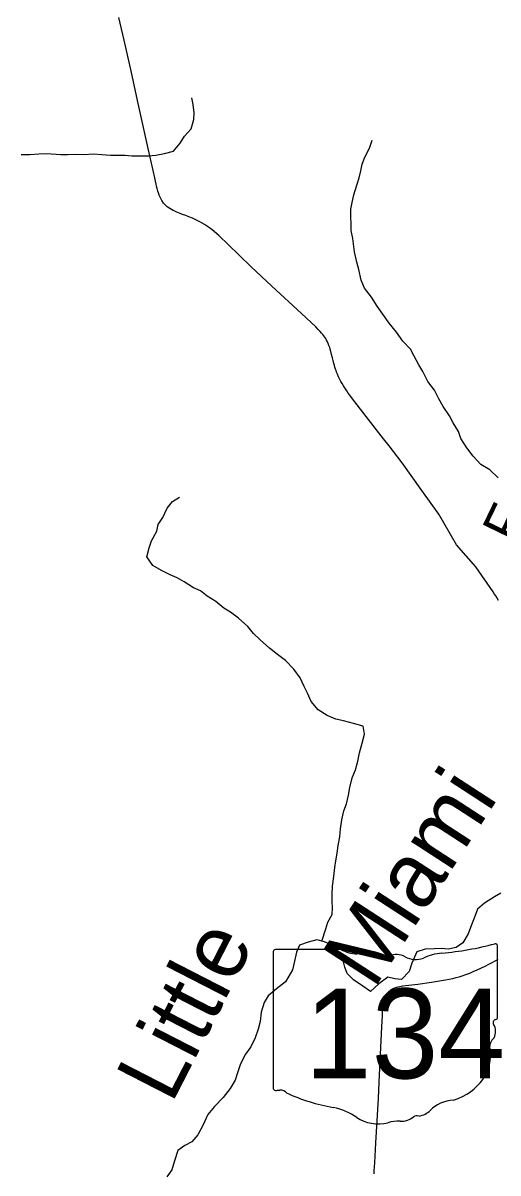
# Model space of a CAD drawing. Extents: x 0 to 1052, y -194 to 246.
# Drawn here: x 3.805 to 4.503, y 17.846 to 19.536 of the extents above; entities that cross this region are included whole.
import ezdxf

# ---------------------------------------------------------------- set-up
doc = ezdxf.new("R2010")
doc.units = 0
for name, color, linetype in [('GM_X_County_Road_Text', 7, 'Continuous'), ('GM_X_Major_River', 7, 'Continuous'), ('GM_X_Major_River_Text', 7, 'Continuous'), ('GM_X_Minor_River', 7, 'Continuous'), ('GM_X_State_Location', 7, 'Continuous'), ('GM_X_State_Route', 7, 'Continuous'), ('GM_X_State_Shield', 7, 'Continuous')]:
    doc.layers.add(name, color=color, linetype=linetype)

msp = doc.modelspace()

# ---------------------------------------------------------------- linework, layer by layer
at = {"layer": 'GM_X_Major_River'}
msp.add_lwpolyline([(4.5075, 18.2574), (4.4979, 18.2519), (4.4833, 18.2424), (4.4732, 18.2338), (4.468, 18.2207), (4.4644, 18.2105), (4.4595, 18.1973), (4.4517, 18.1842), (4.442, 18.1775), (4.4298, 18.1751), (4.42, 18.1761), (4.4094, 18.1755), (4.3961, 18.1751), (4.3838, 18.1708), (4.3767, 18.1546), (4.3726, 18.1421), (4.3613, 18.1302), (4.3515, 18.1312), (4.3413, 18.1337), (4.3282, 18.1241), (4.3158, 18.1125), (4.3046, 18.1204), (4.2911, 18.1301), (4.2814, 18.139), (4.2782, 18.1486), (4.2758, 18.1581), (4.2707, 18.1685), (4.2618, 18.1797), (4.2483, 18.1856), (4.2369, 18.1885), (4.2243, 18.185), (4.2113, 18.1807), (4.207, 18.1705), (4.204, 18.1573), (4.2011, 18.1445), (4.1909, 18.1268), (4.1777, 18.1165), (4.1654, 18.1065), (4.1595, 18.0967), (4.1554, 18.0824), (4.1536, 18.0688), (4.1507, 18.0574), (4.1466, 18.0446), (4.1399, 18.0315), (4.1321, 18.0206), (4.1249, 18.0063), (4.1205, 17.9932), (4.1168, 17.9826), (4.1094, 17.9702), (4.0992, 17.9572), (4.0864, 17.9437), (4.077, 17.9318), (4.0695, 17.916), (4.062, 17.9021), (4.0534, 17.892), (4.0431, 17.8866), (4.0327, 17.8792), (4.0278, 17.8637), (4.0241, 17.8505), (4.0167, 17.8404)], dxfattribs=at)
at = {"layer": 'GM_X_Minor_River'}
for points in [[(3.8025, 19.3424), (3.8154, 19.3426), (3.8283, 19.3436), (3.8397, 19.3442), (3.861, 19.3424), (3.8708, 19.3427), (3.8834, 19.3429), (3.8944, 19.3427), (3.9088, 19.3433), (3.921, 19.3428), (3.9339, 19.3418), (3.9551, 19.3416), (3.965, 19.3407), (3.9783, 19.3405), (3.9897, 19.3407), (4.0003, 19.3414), (4.0133, 19.3442), (4.0263, 19.3475), (4.0363, 19.3591), (4.0425, 19.3693), (4.0525, 19.3805), (4.0561, 19.3938), (4.0566, 19.4036), (4.0553, 19.4158), (4.0531, 19.4257)], [(4.5034, 18.8675), (4.4914, 18.8794), (4.4778, 18.8872), (4.467, 18.8991), (4.4573, 18.9114), (4.4487, 18.9255), (4.4451, 18.9355), (4.4376, 18.9485), (4.4321, 18.9588), (4.4227, 18.9722), (4.4164, 18.9837), (4.4098, 18.9963), (4.4001, 19.0089), (4.3927, 19.0238), (4.3871, 19.0334), (4.3801, 19.046), (4.3745, 19.0567), (4.3636, 19.0683), (4.3539, 19.0817), (4.3431, 19.0947), (4.3364, 19.1043), (4.3256, 19.1196), (4.3174, 19.133), (4.3073, 19.146), (4.3022, 19.1579), (4.2986, 19.1735), (4.2957, 19.1845), (4.2925, 19.1994), (4.2897, 19.2192), (4.2876, 19.231), (4.2873, 19.2405), (4.2871, 19.2507), (4.2872, 19.2621), (4.2889, 19.2719), (4.2913, 19.2833), (4.2957, 19.2977), (4.2992, 19.3083), (4.3016, 19.3185), (4.3037, 19.3283), (4.3076, 19.3385), (4.3142, 19.3517), (4.3182, 19.3634)], [(4.2445, 18.1866), (4.2503, 18.2046), (4.2531, 18.2144), (4.2593, 18.2261), (4.2598, 18.2356), (4.2596, 18.2454), (4.2597, 18.2553), (4.2602, 18.2674), (4.2619, 18.2815), (4.2633, 18.2947), (4.2649, 18.3046), (4.267, 18.3159), (4.2686, 18.3273), (4.2707, 18.3398), (4.2716, 18.3516), (4.2737, 18.3648), (4.2765, 18.3781), (4.2805, 18.3883), (4.2837, 18.4011), (4.2857, 18.4125), (4.289, 18.4265), (4.2937, 18.4382), (4.2973, 18.4511), (4.2997, 18.4636), (4.3037, 18.4776), (4.3073, 18.4908), (4.3052, 18.5026), (4.2908, 18.5066), (4.276, 18.5106), (4.2651, 18.513), (4.2522, 18.5181), (4.239, 18.5266), (4.2289, 18.5389), (4.2234, 18.5511), (4.2186, 18.5607), (4.2127, 18.5737), (4.2034, 18.5863), (4.191, 18.599), (4.179, 18.6079), (4.1673, 18.6171), (4.1538, 18.6295), (4.1441, 18.6387), (4.1358, 18.6491), (4.1219, 18.6614), (4.1103, 18.6699), (4.1005, 18.6761), (4.0885, 18.6857), (4.0757, 18.6935), (4.0659, 18.7012), (4.0557, 18.7059), (4.0418, 18.7148), (4.0316, 18.7206), (4.0214, 18.725), (4.0085, 18.7312), (3.9961, 18.7386), (3.9872, 18.7516), (3.9908, 18.7648), (3.9939, 18.775), (4.0017, 18.789), (4.0038, 18.7988), (4.0107, 18.8094), (4.017, 18.823), (4.0251, 18.8327), (4.0351, 18.839)]]:
    msp.add_lwpolyline(points, dxfattribs=at)
at = {"layer": 'GM_X_State_Route'}
for points in [[(4.504, 18.6871), (4.502, 18.6907), (4.4999, 18.6939), (4.4982, 18.6966), (4.496, 18.7), (4.4706, 18.7369), (4.4423, 18.7689), (4.4161, 18.8139), (4.3914, 18.849), (4.3624, 18.8893), (4.3432, 18.9144), (4.335, 18.9246), (4.3095, 18.9576), (4.2879, 18.9857), (4.2856, 18.9888), (4.2832, 18.9921), (4.281, 18.9952), (4.2781, 18.9996), (4.2761, 19.0025), (4.2741, 19.006), (4.2723, 19.009), (4.2705, 19.0127), (4.269, 19.0157), (4.2673, 19.0196), (4.266, 19.0226), (4.2652, 19.0251), (4.2644, 19.0272), (4.2634, 19.0303), (4.2628, 19.0327), (4.2621, 19.0354), (4.2609, 19.04), (4.2599, 19.0439), (4.2588, 19.0485), (4.2577, 19.0533), (4.2568, 19.0564), (4.2559, 19.0592), (4.2548, 19.062), (4.2537, 19.0649), (4.2525, 19.0675), (4.2514, 19.0699), (4.2501, 19.0721), (4.2489, 19.0741), (4.2475, 19.0759), (4.246, 19.078), (4.2441, 19.0802), (4.2419, 19.0826), (4.2392, 19.0854), (4.2354, 19.0892), (4.2146, 19.1087), (4.1707, 19.1491), (4.1403, 19.1777), (4.1225, 19.195), (4.1074, 19.2098), (4.093, 19.2234), (4.09, 19.2261), (4.0861, 19.2296), (4.0832, 19.2319), (4.0793, 19.2349), (4.0763, 19.2369), (4.0721, 19.2397), (4.0686, 19.2417), (4.0652, 19.2437), (4.0613, 19.2456), (4.0574, 19.2475), (4.0541, 19.2489), (4.0489, 19.2511), (4.0443, 19.2528), (4.0396, 19.2545), (4.0359, 19.2559), (4.0314, 19.2577), (4.0285, 19.2591), (4.0257, 19.2604), (4.0209, 19.2633), (4.0172, 19.2658), (4.0143, 19.2684), (4.0118, 19.2712), (4.0092, 19.2749), (4.0071, 19.2787), (4.0053, 19.2828), (4.0041, 19.286), (4.0033, 19.2888), (4.0024, 19.2925), (4.0015, 19.296), (4.0008, 19.2991), (3.9998, 19.3034), (3.9988, 19.3081), (3.9891, 19.3512), (3.9743, 19.4173), (3.9644, 19.4628), (3.9537, 19.5107), (3.9461, 19.544)], [(4.3212, 17.8447), (4.3215, 17.8491), (4.3218, 17.8553), (4.3221, 17.8608), (4.3235, 17.8906), (4.3276, 17.9557), (4.3288, 17.9793), (4.3305, 18.0202), (4.3325, 18.0606), (4.3334, 18.0773), (4.3337, 18.0836), (4.3343, 18.0901), (4.3347, 18.0937), (4.3351, 18.0967), (4.336, 18.1004), (4.3368, 18.1026), (4.3375, 18.1046), (4.3383, 18.1063), (4.3395, 18.1081), (4.3408, 18.1101), (4.3415, 18.1111), (4.343, 18.1128), (4.3447, 18.1143), (4.3464, 18.1155), (4.3484, 18.1168), (4.3503, 18.1178), (4.353, 18.1188), (4.3561, 18.1196), (4.3588, 18.1201), (4.3631, 18.1209), (4.3724, 18.1222), (4.3854, 18.1237), (4.4057, 18.1266), (4.4259, 18.1297), (4.4315, 18.1308), (4.4369, 18.1318), (4.4416, 18.1331), (4.4464, 18.1344), (4.4508, 18.1359), (4.4558, 18.1376), (4.4591, 18.1389), (4.4617, 18.1399), (4.4678, 18.1424), (4.4718, 18.1442), (4.4791, 18.1475), (4.4845, 18.1501), (4.4897, 18.1527), (4.4949, 18.1555), (4.5, 18.1583), (4.5034, 18.1603)]]:
    msp.add_lwpolyline(points, dxfattribs=at)
at = {"layer": 'GM_X_State_Shield'}
for p, q in [((4.173, 18.1711), (4.173, 17.971)), ((4.2728, 18.1745), (4.1762, 18.1745)), ((4.5026, 18.0748), (4.5026, 18.1795)), ((4.5025, 18.0748), (4.5026, 18.0748))]:
    msp.add_line(p, q, dxfattribs=at)
for centre, major_axis, start_param, end_param in [((4.3852, 18.4474), (0.3495, 0), 4.814394, 5.042369), ((4.4989, 18.1799), (0.00367, 0), 6.141152, 7.989035), ((4.1768, 18.1715), (0.00382, 0), 1.712693, 3.28349), ((4.2957, 18.1978), (0.037, 0), 4.042523, 4.731795), ((4.308, 18.0622), (0.133, 0), 1.404758, 1.657858), ((4.3382, 18.1725), (0.0107, 0), 3.836095, 5.185415), ((4.3539, 18.1494), (0.0222, 0), 0.950623, 2.079405), ((4.4297, 18.1134), (0.0703, 0), 1.699011, 2.107814), ((4.3826, 18.1811), (0.0267, 0), 4.081561, 5.145723), ((4.5017, 18.0671), (0.00568, 0), 1.883978, 3.671073), ((4.4656, 18.0539), (0.0341, 0), 5.934695, 6.695948), ((4.4987, 18.0744), (0.00393, 0), 5.05454, 6.418171), ((4.5157, 18.031), (0.0248, 0), 2.387724, 3.262537), ((4.4047, 18.0177), (0.0874, 0), 5.101752, 6.440018), ((4.1768, 17.9705), (0.00385, 0), 3.00124, 4.508301), ((4.1774, 17.991), (0.0294, 0), 4.665946, 4.897461), ((4.1834, 17.9594), (0.0106, 0), 0.519207, 1.627899), ((4.3172, 18.1392), (0.2524, 0), 4.195997, 4.488961), ((4.4416, 17.9148), (0.0479, 0), 1.647645, 2.488434), ((4.242, 17.8811), (0.079, 0), 0.823519, 1.323587), ((4.36, 17.9434), (0.0267, 0), 4.691044, 5.507374), ((4.3842, 17.9241), (0.00752, 0), 1.147584, 2.315152), ((4.3809, 17.9516), (0.0282, 0), 4.937069, 5.64225), ((4.3274, 17.9584), (0.0501, 0), 4.026481, 4.996735), ((4.3563, 17.8892), (0.0412, 0), 1.495662, 1.94098)]:
    msp.add_ellipse(centre, major_axis=major_axis, ratio=0.8, start_param=start_param, end_param=end_param, dxfattribs=at)

# ---------------------------------------------------------------- texts
at = {"layer": 'GM_X_County_Road_Text'}
msp.add_text('F', height=0.0568, rotation=64.2169, dxfattribs=at).set_placement((4.5295, 18.7683))
at = {"layer": 'GM_X_Major_River_Text'}
for s, rotation, p in [('Miami', 57.0037, (4.3206, 18.1146)), ('Little', 62.8288, (4.0234, 17.9461))]:
    msp.add_text(s, height=0.0947, rotation=rotation, dxfattribs=at).set_placement(p)
at = {"layer": 'GM_X_State_Location'}
for s in ['s', 'r']:
    msp.add_text(s, height=0.000189, dxfattribs=at).set_placement((4.3341, 18.0577))
msp.add_text('134', height=0.000189, rotation=0, dxfattribs=at).set_placement((4.2672, 18.0439))
at = {"layer": 'GM_X_State_Shield'}
msp.add_text('134', height=0.13184, dxfattribs=at).set_placement((4.2195, 17.9851))

doc.saveas('drawing.dxf')
